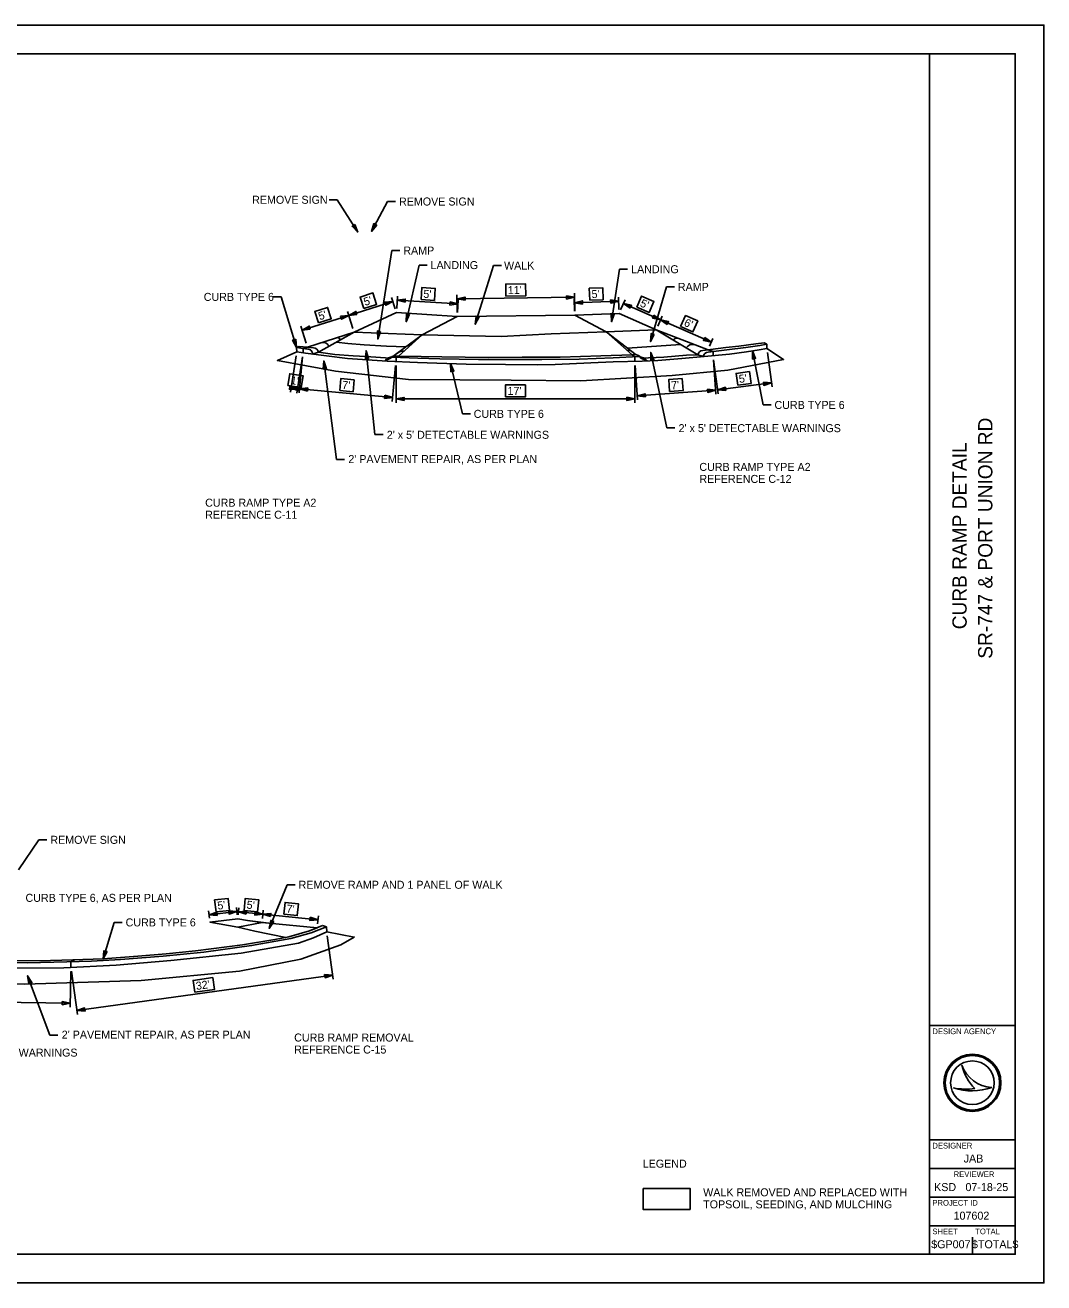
# Model space of a CAD drawing. Extents: x 0 to 680, y 0 to 440.
# Drawn here: x 323.6 to 680, y 0 to 440 of the extents above; entities that cross this region are included whole.
import ezdxf

# ---------------------------------------------------------------- set-up
doc = ezdxf.new("R2010")
doc.units = 0
for name, color, linetype in [('SH_Border', 7, 'Continuous'), ('SH_Cut_Line', 7, 'Continuous'), ('SH_Data', 7, 'Continuous'), ('SH_Text', 7, 'Continuous')]:
    doc.layers.add(name, color=color, linetype=linetype)

msp = doc.modelspace()

# ---------------------------------------------------------------- linework, layer by layer
at = {"layer": 'SH_Border'}
for p, q in [((640, 10), (640, 430)), ((640, 90), (670, 90)), ((640, 50), (670, 50)), ((640, 40), (670, 40)), ((640, 30), (670, 30)), ((640, 20), (670, 20))]:
    msp.add_line(p, q, dxfattribs=at)
msp.add_lwpolyline([(30, 430), (670, 430), (670, 10), (30, 10)], close=True, dxfattribs=at)
at = {"layer": 'SH_Cut_Line'}
msp.add_lwpolyline([(0, 0), (680, 0), (680, 440), (0, 440)], close=True, dxfattribs=at)
at = {"layer": 'SH_Data'}
for p, q in [((651.35, 76.19), (651.35, 76.19)), ((648.34, 68.19), (648.34, 68.19)), ((655, 70), (655, 70)), ((661.75, 68.37), (661.75, 68.37)), ((647.5, 13.5), (647.5, 13.5)), ((655, 10), (655, 16))]:
    msp.add_line(p, q, dxfattribs=at)
for radius in [10, 9.54, 9.54, 7.64]:
    msp.add_circle((655, 70), radius, dxfattribs=at)
for centre, radius, start, end in [((662.32, 79.95), 11.6, 198.9257, 198.9319), ((666.93, 79.4), 15.91, 191.6379, 191.6421), ((662.32, 79.95), 11.6, 198.9319, 267.1657), ((666.93, 79.4), 15.91, 191.6421, 226.0947), ((654.79, 87.4), 20.26, 251.4576, 290.0832), ((652.96, 93.09), 25.32, 259.4964, 259.4995), ((654.79, 87.4), 20.26, 251.4527, 251.4576), ((652.96, 93.09), 25.32, 259.4995, 276.6672)]:
    msp.add_arc(centre, radius, start, end, dxfattribs=at)
at = {"layer": 'SH_Text'}
for p, q in [((429.91, 378.9), (432.71, 378.9)), ((439.93, 367.58), (432.71, 378.9)), ((444.77, 367.84), (450.35, 378.29)), ((453.15, 378.29), (450.35, 378.29)), ((446.96, 330.19), (451.86, 361.15)), ((454.66, 361.15), (451.86, 361.15)), ((456.93, 336.25), (461.4, 356.05)), ((464.2, 356.05), (461.4, 356.05)), ((481.04, 335.39), (487.39, 355.9)), ((490.19, 355.9), (487.39, 355.9)), ((528.69, 336.25), (531.58, 354.6)), ((534.38, 354.6), (531.58, 354.6)), ((542.38, 329.28), (547.93, 348.43)), ((550.73, 348.43), (547.93, 348.43)), ((410.37, 344.92), (413.17, 344.92)), ((418.5, 327.24), (413.17, 344.92)), ((436.78, 338.48), (452.24, 343.37)), ((453.06, 340.76), (451.81, 344.7)), ((453.57, 340.82), (453.84, 345.2)), ((453.76, 343.8), (475.03, 342.47)), ((474.74, 339.5), (474.67, 345.69)), ((474.68, 344.29), (515.82, 344.78)), ((474.84, 339.5), (475.12, 343.87)), ((515.84, 339.99), (515.7, 344.3)), ((515.75, 342.9), (531.22, 343.42)), ((515.87, 339.99), (515.8, 346.18)), ((531.31, 340.5), (531.17, 344.82)), ((531.93, 340.38), (533.5, 343.93)), ((438.24, 333.87), (436.36, 339.81)), ((532.93, 342.65), (545.91, 336.91)), ((421.95, 328.72), (420.07, 334.66)), ((420.49, 333.32), (436.78, 338.48)), ((462.53, 331.71), (474.76, 338.1)), ((526.84, 332.75), (515.89, 338.59)), ((544.9, 334.64), (546.47, 338.19)), ((545.91, 336.91), (563.66, 329.06)), ((422.37, 327.38), (438.66, 332.54)), ((462.53, 331.71), (438.66, 332.54)), ((454.25, 324.16), (462.53, 331.71)), ((526.84, 332.75), (544.33, 333.36)), ((563.07, 327.72), (564.23, 330.34)), ((420.84, 326.83), (418.5, 327.24)), ((419.46, 327.62), (422.37, 327.38)), ((420.84, 326.83), (420.8, 325.37)), ((424.48, 327.12), (422.37, 327.38)), ((442.87, 326.09), (445.98, 296.78)), ((534.37, 327.01), (552.88, 328.28)), ((560.63, 326.2), (568.75, 327.22)), ((562.57, 325.59), (569.12, 326.45)), ((578.05, 326.06), (581.8, 307.12)), ((418.38, 324.32), (416.44, 311.62)), ((420.59, 323.98), (418.65, 311.29)), ((420.67, 323.97), (419.49, 311.37)), ((426.17, 325.58), (424.1, 324.94)), ((428.05, 322.53), (432.52, 287.99)), ((451.36, 323.47), (449.53, 322.54)), ((452.81, 324.17), (454.25, 324.16)), ((472.39, 321.6), (476.56, 304)), ((535.91, 324.72), (536.78, 324.73)), ((539.04, 323.45), (541.25, 322.53)), ((542.44, 325.53), (548.07, 299.09)), ((558.89, 324.7), (560.75, 324.03)), ((564.38, 322.96), (565.26, 310.89)), ((564.47, 322.97), (566.08, 310.99)), ((583.3, 325.5), (584.91, 313.52)), ((453.21, 320.94), (452.04, 308.34)), ((453.34, 320.93), (453.35, 307.82)), ((536.87, 320.97), (536.88, 307.86)), ((536.97, 320.98), (537.84, 308.91)), ((416.65, 313.01), (418.86, 312.67)), ((419.62, 312.77), (452.17, 309.73)), ((565.89, 312.38), (584.72, 314.91)), ((453.35, 309.22), (536.88, 309.26)), ((537.74, 310.3), (565.16, 312.29)), ((479.36, 304), (476.56, 304)), ((584.6, 307.12), (581.8, 307.12)), ((448.78, 296.78), (445.98, 296.78)), ((550.87, 299.09), (548.07, 299.09)), ((435.32, 287.99), (432.52, 287.99)), ((321.23, 144.51), (328.36, 154.98)), ((331.16, 154.98), (328.36, 154.98)), ((408.98, 123.98), (415.22, 139.27)), ((418.02, 139.27), (415.22, 139.27)), ((388.05, 127.6), (387.75, 130.17)), ((397.66, 129.91), (387.91, 128.78)), ((397.79, 128.73), (397.49, 131.3)), ((398.09, 128.73), (398.34, 131.2)), ((406.73, 128.96), (398.2, 129.8)), ((406.58, 127.52), (406.87, 130.35)), ((426.04, 127.04), (406.73, 128.96)), ((425.89, 125.6), (426.17, 128.44)), ((350.86, 113.35), (354.77, 126.09)), ((357.57, 126.09), (354.77, 126.09)), ((397.96, 124.48), (406.45, 126.12)), ((429.29, 121.4), (431.39, 106.26)), ((324.41, 107.44), (332.25, 86.63)), ((339.55, 108.97), (339.35, 96.39)), ((339.77, 108.99), (341.86, 93.85)), ((341.67, 95.24), (431.19, 107.65)), ((288.28, 98.6), (339.38, 97.79)), ((335.05, 86.63), (332.25, 86.63))]:
    msp.add_line(p, q, dxfattribs=at)
for points in [[(438.9, 370.24), (439.93, 367.58), (437.96, 369.64)], [(446.59, 370.05), (444.77, 367.84), (445.6, 370.57)], [(462.09, 343.98), (466.78, 343.69), (467.05, 347.88), (462.35, 348.18)], [(491.77, 345.2), (498.71, 345.28), (498.66, 349.48), (491.72, 349.4)], [(521.11, 343.78), (525.81, 343.94), (525.67, 348.14), (520.97, 347.98)], [(442.06, 340.88), (446.54, 342.3), (445.27, 346.3), (440.79, 344.89)], [(449.4, 343.06), (452.24, 343.37), (449.74, 341.99)], [(456.52, 343.07), (453.76, 343.8), (456.59, 344.19)], [(472.27, 343.21), (475.03, 342.47), (472.2, 342.09)], [(477.49, 343.77), (474.68, 344.29), (477.48, 344.89)], [(513.01, 345.31), (515.82, 344.78), (513.02, 344.19)], [(518.56, 342.44), (515.75, 342.9), (518.53, 343.56)], [(528.4, 343.88), (531.22, 343.42), (528.44, 342.76)], [(537.55, 341.37), (541.85, 339.47), (543.55, 343.31), (539.25, 345.22)], [(426.18, 335.86), (430.67, 337.28), (429.4, 341.28), (424.92, 339.86)], [(439.62, 338.79), (436.78, 338.48), (439.29, 339.86)], [(458.09, 338.86), (456.93, 336.25), (457, 339.11)], [(529.68, 338.93), (528.69, 336.25), (528.57, 339.11)], [(535.27, 341.01), (532.93, 342.65), (535.72, 342.03)], [(423.33, 333.63), (420.49, 333.32), (422.99, 334.7)], [(433.95, 338.17), (436.78, 338.48), (434.28, 337.1)], [(482.4, 337.9), (481.04, 335.39), (481.33, 338.23)], [(543.57, 338.56), (545.91, 336.91), (543.12, 337.53)], [(548.24, 335.27), (545.91, 336.91), (548.69, 336.29)], [(552.92, 334.58), (557.22, 332.67), (558.92, 336.51), (554.62, 338.42)], [(418.23, 330.09), (418.5, 327.24), (417.16, 329.76)], [(447.95, 332.87), (446.96, 330.19), (446.84, 333.05)], [(543.7, 331.82), (542.38, 329.28), (542.62, 332.13)], [(561.33, 330.7), (563.66, 329.06), (560.88, 329.68)], [(442.61, 323.25), (442.87, 326.09), (443.72, 323.37)], [(578.05, 323.2), (578.05, 326.06), (579.15, 323.42)], [(427.85, 319.68), (428.05, 322.53), (428.96, 319.82)], [(472.49, 318.75), (472.39, 321.6), (473.58, 319)], [(542.47, 322.68), (542.44, 325.53), (543.57, 322.91)], [(415.53, 313.88), (420.19, 313.18), (420.82, 317.33), (416.17, 318.04)], [(572.88, 314.02), (577.55, 314.65), (576.99, 318.81), (572.32, 318.19)], [(416.18, 313.65), (418.86, 312.67), (416.01, 312.54)], [(419.33, 312.03), (416.65, 313.01), (419.5, 313.14)], [(422.36, 311.95), (419.62, 312.77), (422.46, 313.07)], [(433.62, 312.17), (438.3, 311.73), (438.69, 315.91), (434.01, 316.35)], [(491.64, 309.94), (498.58, 309.94), (498.58, 314.14), (491.64, 314.14)], [(549.05, 311.82), (553.75, 312.16), (553.44, 316.35), (548.75, 316.01)], [(562.32, 312.64), (565.16, 312.29), (562.4, 311.53)], [(568.74, 312.2), (565.89, 312.38), (568.59, 313.31)], [(581.87, 315.09), (584.72, 314.91), (582.02, 313.98)], [(449.43, 310.55), (452.17, 309.73), (449.33, 309.43)], [(456.15, 308.66), (453.35, 309.22), (456.15, 309.78)], [(534.07, 309.82), (536.88, 309.26), (534.08, 308.7)], [(540.58, 309.95), (537.74, 310.3), (540.49, 311.06)], [(390.37, 129.77), (395.04, 130.31), (394.55, 134.49), (389.88, 133.94)], [(400.19, 130.31), (404.87, 129.84), (405.29, 134.02), (400.61, 134.49)], [(414.11, 128.93), (418.79, 128.46), (419.21, 132.64), (414.52, 133.11)], [(390.76, 128.55), (387.91, 128.78), (390.63, 129.66)], [(394.81, 130.15), (397.66, 129.91), (394.94, 129.03)], [(400.93, 128.97), (398.2, 129.8), (401.04, 130.08)], [(404, 129.79), (406.73, 128.96), (403.89, 128.68)], [(409.46, 128.12), (406.73, 128.96), (409.57, 129.24)], [(423.3, 127.88), (426.04, 127.04), (423.19, 126.76)], [(397.96, 124.48), (388.21, 126.21), (397.96, 127.34), (401.4, 126.73), (406.45, 126.12)], [(408.82, 125.84), (425.75, 124.21), (423.1, 123.13), (415.85, 121.03), (414.74, 120.83), (403.93, 123.05), (397.96, 124.48), (406.45, 126.12)], [(410.56, 126.36), (408.98, 123.98), (409.52, 126.78)], [(352.22, 115.87), (350.86, 113.35), (351.15, 116.19)], [(324.87, 104.62), (324.41, 107.44), (325.92, 105.02)], [(382.9, 101.66), (389.77, 102.61), (389.2, 106.77), (382.32, 105.82)], [(428.34, 107.82), (431.19, 107.65), (428.5, 106.71)], [(336.58, 98.4), (339.38, 97.79), (336.57, 97.28)], [(344.52, 95.07), (341.67, 95.24), (344.37, 96.18)], [(539.78, 33.04), (556.24, 33.04), (556.24, 25.69), (539.78, 25.69)], [(539.78, 33.04), (556.24, 33.04), (556.24, 25.69), (539.78, 25.69)]]:
    msp.add_lwpolyline(points, close=True, dxfattribs=at)
for points in [[(426.17, 325.58), (438.66, 332.54), (453.48, 339.43), (474.76, 338.1), (515.89, 338.59), (531.36, 339.1), (531.36, 339.1)], [(531.36, 339.1), (544.33, 333.36), (558.89, 324.7)], [(451.36, 323.47), (462.53, 331.71), (490.08, 331.13), (507.63, 331.97), (526.84, 332.75), (537.38, 324.72)], [(536.87, 322.37), (536.85, 323.97), (535.91, 324.72), (526.84, 332.75)], [(564.28, 324.36), (564.34, 325.82), (562.5, 326.44), (544.33, 333.36)], [(418.59, 325.71), (411.84, 322.63), (432.19, 318.96), (457.74, 316.06), (493.64, 315.77), (517.95, 315.53), (549.95, 317.42), (569.4, 319.32), (588.92, 322.99), (583.11, 326.89)], [(418.59, 325.71), (418.5, 327.24), (419.46, 327.62)], [(450.18, 322.5), (436.38, 323.42), (421.65, 325.24), (418.59, 325.71)], [(422.37, 327.38), (420.84, 326.83), (422.44, 326.66)], [(432.45, 329.08), (436.43, 328.68), (442.17, 328.16), (450.02, 327.7), (456.8, 327.49)], [(583.11, 326.89), (580.38, 326.44), (575.97, 325.72), (570.07, 324.89), (561.19, 324.07), (553.35, 323.35), (544.95, 322.69), (539.47, 322.45), (529.32, 322.16), (521.45, 321.81), (508.96, 321.3), (502.95, 321.22), (491.61, 321.33), (477.89, 321.44), (460.86, 321.93), (450.18, 322.5)], [(582.2, 328.88), (579.28, 328.47), (573.3, 327.67), (568.75, 327.22)], [(583.07, 328.34), (580.61, 327.94), (575.69, 327.22), (569.12, 326.45)], [(583.11, 326.89), (583.07, 328.34), (582.2, 328.88)], [(426.17, 325.58), (431.96, 324.79), (438.36, 324.36), (442.78, 324.09), (451.36, 323.47)], [(451.87, 323.84), (460.99, 323.51), (468.7, 323.32), (482.14, 323.04), (494.82, 322.99), (504.33, 323.04), (517.44, 323.18), (529.27, 323.61), (538.28, 324.03)], [(453.34, 322.33), (453.4, 323.79), (454.25, 324.16)], [(454.25, 324.16), (462.18, 324.12), (469.42, 323.93), (477.51, 323.79), (485.69, 323.74), (497.52, 323.84), (510.77, 323.89), (525.01, 324.31), (535.91, 324.72)], [(539.04, 323.45), (547.03, 323.83), (555.01, 324.53), (558.89, 324.7)], [(218.8, 123.66), (211.16, 122.8), (215.83, 117.93), (223.43, 114.48), (237.53, 111.03), (258.62, 108.19), (279.61, 106.37), (323.31, 104.44), (364.18, 105.76), (398.55, 109), (420.05, 113.27), (434.04, 118.24), (438.71, 120.98), (429.1, 122.78)], [(218.8, 123.66), (220.32, 121.78), (223.12, 119.96), (229.77, 117.78), (241.66, 115.44), (252.09, 114.14), (268.66, 112.64), (289.89, 111.08), (304.12, 110.51), (319.43, 110.14), (337.08, 110.25), (355.41, 111.18), (374.57, 112.79), (399.18, 115.34), (419.27, 118.87), (424.5, 120.7), (429.1, 122.78), (428.99, 124.55), (427.63, 124.97)], [(293.53, 112.5), (303.7, 112.44), (315.71, 112.08), (324.38, 111.92), (338.17, 112.25), (346.75, 112.58), (356.88, 113.15), (371.9, 114.25), (386.12, 115.74), (402.8, 117.97), (416.49, 120.43), (423.67, 122.43), (428.99, 124.55)], [(293.88, 113.49), (299.03, 113.39), (309.66, 113.09), (318.96, 112.79), (328.6, 112.69), (340.23, 112.99), (350.86, 113.35), (362.99, 114.28), (372.89, 115.08), (383.19, 116.15), (399.64, 118.31), (410.9, 120.14), (415.85, 121.03), (423.1, 123.13), (427.63, 124.97)], [(414.74, 120.83), (403.93, 123.05), (397.96, 124.48), (388.21, 126.21), (397.96, 127.34), (401.4, 126.73), (408.82, 125.84), (425.75, 124.21)], [(339.57, 110.37), (339.59, 112.31), (340.79, 113.01)]]:
    msp.add_lwpolyline(points, dxfattribs=at)
for centre, radius, start, end in [((432.84, 329.71), 0.964, 6.899, 94.2463), ((551.62, 329.27), 1.27, 83.6077, 158.7894), ((422.46, 325.01), 1.64, 357.3479, 90.5981), ((424.35, 325.27), 1.85, 9.7234, 86.0294), ((427.85, 327), 2.05, 17.2907, 97.6817), ((455.84, 322.4), 3.52, 84.6992, 125.015), ((458.78, 324.62), 3.49, 93.4024, 122.2167), ((531.77, 327.52), 1.18, 48.5664, 104.7663), ((534.62, 324.08), 2.18, 54.1733, 100.6216), ((557.13, 325.68), 2.64, 76.362, 147.9565), ((560.84, 324.19), 2.02, 95.9621, 165.3462), ((451.89, 321.06), 2.78, 82.9823, 147.795), ((452.67, 322.6), 1.58, 85.1258, 146.5914), ((537.05, 322.57), 2.18, 23.9778, 97.0715), ((538.09, 319.97), 4.07, 38.9337, 87.2931), ((562.68, 323.63), 1.97, 93.2225, 168.2508)]:
    msp.add_arc(centre, radius, start, end, dxfattribs=at)

# ---------------------------------------------------------------- texts
at = {"layer": 'SH_Data'}
for s, p in [('SR-747 & PORT UNION RD', (662, 218.35)), ('CURB RAMP DETAIL', (653, 228.64))]:
    msp.add_text(s, height=5, rotation=90, dxfattribs=at).set_placement(p)
for s, height, p in [('DESIGN AGENCY', 2, (641, 87)), ('DESIGNER', 2, (641, 47)), ('JAB', 2.8, (651.95, 42.1)), ('REVIEWER', 2, (648.44, 37)), ('KSD', 2.8, (641.6, 32.1)), ('07-18-25', 2.8, (652.57, 32.1)), ('PROJECT ID', 2, (641, 27)), ('107602', 2.8, (648.42, 22.1)), ('SHEET', 2, (641, 17)), ('TOTAL', 2, (656, 17)), ('$GP007', 2.8, (640.6, 12.1)), ('$TOTAL$', 2.8, (654.86, 12.1))]:
    msp.add_text(s, height=height, dxfattribs=at).set_placement(p)
at = {"layer": 'SH_Text'}
for s, p in [('REMOVE SIGN', (402.99, 377.51)), ('REMOVE SIGN', (454.38, 376.9)), ('RAMP', (455.88, 359.76)), ('LANDING', (465.41, 354.66)), ('WALK', (491.12, 354.51)), ('LANDING', (535.59, 353.21)), ('RAMP', (551.95, 347.03)), ('CURB TYPE 6', (386.07, 343.53)), ('CURB TYPE 6', (585.75, 305.73)), ('CURB TYPE 6', (480.52, 302.61)), ("2' x 5' DETECTABLE WARNINGS", (552.2, 297.61)), ("2' x 5' DETECTABLE WARNINGS", (450.11, 295.29)), ("2' PAVEMENT REPAIR, AS PER PLAN", (436.65, 286.8)), ('CURB RAMP TYPE A2', (559.48, 284.05)), ('REFERENCE C-12', (559.48, 279.85)), ('CURB RAMP TYPE A2', (386.56, 271.53)), ('REFERENCE C-11', (386.56, 267.33)), ('REMOVE SIGN', (332.39, 153.59)), ('REMOVE RAMP AND 1 PANEL OF WALK', (419.25, 137.87)), ('CURB TYPE 6, AS PER PLAN', (323.69, 133.29)), ('CURB TYPE 6', (358.72, 124.7)), ("2' PAVEMENT REPAIR, AS PER PLAN", (336.38, 85.43)), ('CURB RAMP REMOVAL', (417.71, 84.42)), ("2' x 5' DETECTABLE WARNINGS", (285.12, 79.15)), ('REFERENCE C-15', (417.71, 80.22)), ('LEGEND', (539.65, 40.29)), ('WALK REMOVED AND REPLACED WITH', (560.8, 30.27)), ('TOPSOIL, SEEDING, AND MULCHING', (560.8, 26.07))]:
    msp.add_text(s, height=2.8, dxfattribs=at).set_placement(p)
for s, rotation, p in [("11'", 0.6798, (492.46, 345.9)), ("5'", 17.557, (442.51, 341.76)), ("5'", 356.4323, (462.83, 344.64)), ("5'", 1.9018, (521.78, 344.5)), ("5'", 336.1353, (538.47, 341.73)), ("5'", 17.557, (426.64, 336.74)), ("6'", 336.1353, (553.84, 334.93)), ("1'", 351.3234, (416.33, 314.47)), ("5'", 7.6588, (573.48, 314.81)), ("7'", 354.6694, (434.38, 312.8)), ("17'", 0.028, (492.34, 310.64)), ("7'", 4.141, (549.7, 312.57)), ("5'", 6.623, (390.98, 130.55)), ("5'", 354.3377, (400.96, 130.94)), ("7'", 354.3377, (414.87, 129.56)), ("32'", 7.891, (383.5, 102.45))]:
    msp.add_text(s, height=2.8, rotation=rotation, dxfattribs=at).set_placement(p)

doc.saveas('drawing.dxf')
